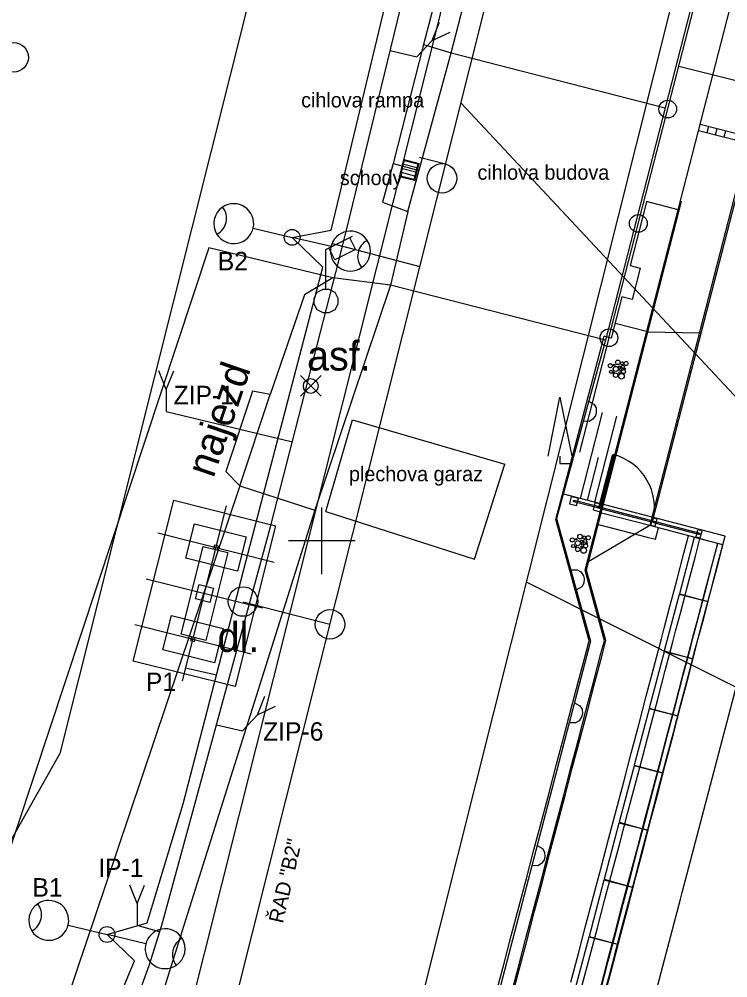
# Model space of a CAD drawing. Extents: x -733601 to -733291, y -1137892 to -1137187.
# Drawn here: x -733460.25 to -733436.26, y -1137614.8 to -1137582.33 of the extents above; entities that cross this region are included whole.
import ezdxf

# ---------------------------------------------------------------- set-up
doc = ezdxf.new("R2010")
doc.units = 0
for name, color, linetype in [('Default', 7, 'Continuous'), ('Krizky_Hektom_sit', 7, 'Continuous'), ('SIT_PROJ', 7, 'Continuous'), ('SIT_PUV_BUS', 7, 'Continuous'), ('SIT_PUV_ZELEZNICE', 7, 'Continuous')]:
    doc.layers.add(name, color=color, linetype=linetype)

# ---------------------------------------------------------------- blocks, each defined once
blk = doc.blocks.new('DOPRAVA_4$0$SYMB1230')
at = {"layer": 'Default'}
for p, q in [((-0.1, -0.329897), (-0.1, -0.020619)), ((0, -0.020619), (0, -0.329897)), ((0.1, -0.020619), (0.1, -0.329897)), ((-0.1, -0.325773), (-0.1, -0.329897))]:
    blk.add_line(p, q, dxfattribs=at)
for points in [[(-0.2, 0), (0.2, 0), (0.2, -0.35), (-0.2, -0.35)], [(-0.182831, -0.020619), (0.181696, -0.020619), (0.181696, -0.329897), (-0.182831, -0.329897)]]:
    blk.add_lwpolyline(points, close=True, dxfattribs=at)
blk = doc.blocks.new('novy_s_2r')
at = {"layer": 'Default'}
for p in [(502.569, 387.82), (502.559, 384.813)]:
    blk.add_line(p, (502.564, 386.316), dxfattribs=at)
blk.add_circle((502.564, 386.316), 0.298, dxfattribs=at)
blk.add_circle((502.564, 386.316), 0.298, dxfattribs=at)
blk.add_circle((502.564, 386.316), 0.298, dxfattribs=at)
blk.add_circle((502.564, 386.316), 0.298, dxfattribs=at)
for centre, radius, start, end in [((502.571, 388.57), 0.75, 46.9837, 135.4673), ((502.571, 388.57), 0.75, 46.9837, 135.4673), ((502.571, 388.57), 0.75, 135.4683, 46.9828), ((502.55, 389.547), 0.684, 221.2842, 321.1668), ((502.55, 389.547), 0.684, 221.2842, 321.1668), ((502.556, 384.063), 0.75, 315.4683, 226.9828), ((502.577, 383.086), 0.684, 41.2842, 141.1668), ((502.577, 383.086), 0.684, 41.2842, 141.1668), ((502.556, 384.063), 0.75, 226.9837, 315.4673), ((502.556, 384.063), 0.75, 226.9837, 315.4673)]:
    blk.add_arc(centre, radius, start, end, dxfattribs=at)
blk = doc.blocks.new('VY1')
at = {"layer": 'Default'}
for q in [(-50, 275), (50, 275), (0, 0)]:
    blk.add_line((0, 150), q, dxfattribs=at)
blk = doc.blocks.new('POINT_DISPLAY')
at = {"layer": 'Default'}
for p, q in [((-0.7, -0.7), (0.7, 0.7)), ((-0.7, 0.7), (0.7, -0.7))]:
    blk.add_line(p, q, dxfattribs=at)
blk.add_circle((0, 0), 0.5, dxfattribs=at)
blk = doc.blocks.new('vytyc_bod_MP')
at = {"layer": 'Default'}
blk.add_blockref('POINT_DISPLAY', (0, 0), dxfattribs=at)

msp = doc.modelspace()

# ---------------------------------------------------------------- linework, layer by layer
at = {"layer": 'Krizky_Hektom_sit'}
for p, q in [((-733450, -1137601.131), (-733450, -1137598.869)), ((-733448.869, -1137600), (-733451.131, -1137600))]:
    msp.add_line(p, q, dxfattribs=at)
at = {"layer": 'SIT_PROJ'}
for p, q in [((-733440.281, -1137593.122), (-733430.325, -1137554.381)), ((-733454.719, -1137604.745), (-733453.228, -1137598.809)), ((-733455.553, -1137599.731), (-733451.615, -1137600.72)), ((-733455.943, -1137601.283), (-733452.005, -1137602.272)), ((-733456.332, -1137602.835), (-733452.394, -1137603.823))]:
    msp.add_line(p, q, dxfattribs=at)
for points in [[(-733457.917, -1137622.364), (-733458.777, -1137620.095), (-733456.339, -1137614.218), (-733457.273, -1137613.333), (-733455.913, -1137612.939), (-733454.69, -1137608.9), (-733452.562, -1137600.661), (-733449.967, -1137590.732), (-733451.007, -1137589.721), (-733449.679, -1137589.475), (-733444.067, -1137566.075), (-733444.902, -1137565.405), (-733443.754, -1137565.269), (-733437.875, -1137541.673), (-733438.793, -1137541.042), (-733437.71, -1137541.027), (-733436.525, -1137536.63), (-733452.133, -1137532.662), (-733452.807, -1137531.541)], [(-733456.299, -1137623.235), (-733433.573, -1137532.72)], [(-733443.713, -1137537.937), (-733443.53, -1137546.097), (-733458.871, -1137607.201), (-733463.551, -1137615.482)], [(-733429.102, -1137545.713), (-733449.631, -1137627.477)], [(-733457.917, -1137622.364), (-733458.523, -1137621.757), (-733455.851, -1137614.377), (-733455.422, -1137613.019), (-733451.725, -1137599.481), (-733449.522, -1137590.912), (-733449.164, -1137589.482), (-733443.392, -1137565.741), (-733438.875, -1137547.904)], [(-733454.604, -1137622.264), (-733444.427, -1137581.731)], [(-733447.684, -1137583.394), (-733446.783, -1137583.603)], [(-733437.916, -1137583.919), (-733418.568, -1137588.759), (-733418.568, -1137588.759)], [(-733445.29, -1137585.169), (-733420.477, -1137611.718), (-733420.477, -1137611.718)], [(-733446.689, -1137587.01), (-733445.808, -1137587.231)], [(-733449.644, -1137589.929), (-733446.679, -1137590.702)], [(-733440.281, -1137593.122), (-733441.276, -1137596.996)], [(-733455.265, -1137595.618), (-733450.997, -1137596.65)], [(-733455.016, -1137598.618), (-733451.563, -1137599.485), (-733452.931, -1137604.936), (-733456.384, -1137604.069), (-733455.016, -1137598.619)], [(-733453.536, -1137600.306), (-733453.503, -1137600.177), (-733453.632, -1137600.144), (-733453.665, -1137600.273), (-733453.536, -1137600.306)], [(-733443.08, -1137601.386), (-733424.737, -1137610.597), (-733424.737, -1137610.597)], [(-733452.667, -1137602.059), (-733449.724, -1137602.826)], [(-733454.315, -1137603.409), (-733454.283, -1137603.28), (-733454.412, -1137603.248), (-733454.444, -1137603.377), (-733454.315, -1137603.409)], [(-733453.568, -1137604.551), (-733454.611, -1137604.306)], [(-733453.567, -1137606.228), (-733452.689, -1137606.432)], [(-733455.5, -1137613.237), (-733456.253, -1137613.029)]]:
    msp.add_lwpolyline(points, dxfattribs=at)
for points in [[(-733454.603, -1137600.589), (-733454.311, -1137599.425), (-733452.565, -1137599.863), (-733452.857, -1137601.027)], [(-733454.764, -1137603.159), (-733454.017, -1137600.185), (-733453.183, -1137600.394), (-733453.93, -1137603.369)], [(-733454.277, -1137601.959), (-733454.155, -1137601.474), (-733453.67, -1137601.596), (-733453.792, -1137602.081)], [(-733455.382, -1137603.692), (-733455.09, -1137602.528), (-733453.344, -1137602.966), (-733453.637, -1137604.13)]]:
    msp.add_lwpolyline(points, close=True, dxfattribs=at)
for centre, radius in [((-733460.435, -1137583.625), 0.5), ((-733438.29, -1137585.374), 0.3), ((-733445.931, -1137587.721), 0.5), ((-733439.285, -1137589.248), 0.3), ((-733440.281, -1137593.122), 0.3), ((-733440.281, -1137593.122), 0.3), ((-733452.667, -1137602.054), 0.5), ((-733449.724, -1137602.827), 0.5)]:
    msp.add_circle(centre, radius, dxfattribs=at)
at = {"layer": 'SIT_PUV_BUS'}
for p, q in [((-733445.62, -1137583.47), (-733437, -1137550.03)), ((-733429.79, -1137551.88), (-733440.4, -1137593.2)), ((-733442.47, -1137567.55), (-733446.56, -1137583.19)), ((-733446.56, -1137583.19), (-733447.59, -1137587.22)), ((-733446.56, -1137583.19), (-733445.62, -1137583.47)), ((-733447.09, -1137588.85), (-733445.62, -1137583.47)), ((-733445.62, -1137583.47), (-733438.38, -1137585.33)), ((-733447.59, -1137587.22), (-733447.95, -1137588.53)), ((-733447.59, -1137587.22), (-733446.71, -1137587.46)), ((-733447.95, -1137588.53), (-733447.09, -1137588.85)), ((-733447.09, -1137588.85), (-733447.67, -1137591.34)), ((-733449.86, -1137590.13), (-733448.96, -1137589.68)), ((-733449.06, -1137589.73), (-733448.86, -1137590.13)), ((-733453.82, -1137590.07), (-733460.86, -1137611.32)), ((-733449.63, -1137591.09), (-733453.82, -1137590.07)), ((-733449.86, -1137591.48), (-733449.86, -1137590.13)), ((-733449.56, -1137590.48), (-733449.76, -1137590.08)), ((-733448.86, -1137590.13), (-733449.56, -1137590.48)), ((-733449.63, -1137591.09), (-733450.59, -1137591.67)), ((-733447.67, -1137591.34), (-733449.63, -1137591.09)), ((-733450.26, -1137591.78), (-733450.16, -1137591.58)), ((-733447.67, -1137591.34), (-733450.24, -1137598.96)), ((-733450.16, -1137591.58), (-733449.96, -1137591.48)), ((-733449.96, -1137591.48), (-733449.76, -1137591.48)), ((-733449.76, -1137591.48), (-733449.56, -1137591.58)), ((-733449.56, -1137591.58), (-733449.46, -1137591.78)), ((-733440.4, -1137593.2), (-733447.67, -1137591.34)), ((-733450.59, -1137591.67), (-733451.75, -1137595.04)), ((-733450.26, -1137591.98), (-733450.26, -1137591.78)), ((-733450.16, -1137592.18), (-733450.26, -1137591.98)), ((-733449.46, -1137591.98), (-733449.56, -1137592.18)), ((-733449.46, -1137591.78), (-733449.46, -1137591.98)), ((-733449.96, -1137592.28), (-733450.16, -1137592.18)), ((-733449.76, -1137592.28), (-733449.96, -1137592.28)), ((-733449.56, -1137592.18), (-733449.76, -1137592.28)), ((-733440.4, -1137593.2), (-733442.05, -1137599.24)), ((-733452.35, -1137594.93), (-733453.25, -1137597.65)), ((-733452.78, -1137598.14), (-733451.75, -1137595.04)), ((-733451.75, -1137595.04), (-733452.35, -1137594.93)), ((-733442.34, -1137597.13), (-733441.94, -1137595.13)), ((-733441.94, -1137595.13), (-733441.54, -1137597.13)), ((-733440.968, -1137595.272), (-733440.788, -1137595.373)), ((-733440.788, -1137595.373), (-733440.718, -1137595.496)), ((-733440.718, -1137595.496), (-733440.709, -1137595.654)), ((-733440.823, -1137595.882), (-733440.946, -1137595.952)), ((-733440.735, -1137595.75), (-733440.823, -1137595.882)), ((-733440.709, -1137595.654), (-733440.735, -1137595.75)), ((-733449.86, -1137599.01), (-733448.96, -1137595.9)), ((-733448.96, -1137595.9), (-733443.8, -1137597.4)), ((-733440.946, -1137595.952), (-733441.152, -1137595.948)), ((-733441.94, -1137597.13), (-733441.94, -1137597.38)), ((-733444.83, -1137600.62), (-733443.8, -1137597.4)), ((-733441.94, -1137597.38), (-733441.54, -1137597.38)), ((-733453.25, -1137597.65), (-733452.78, -1137598.14)), ((-733452.78, -1137598.14), (-733457.34, -1137611.69)), ((-733452.78, -1137598.14), (-733450.24, -1137598.96)), ((-733450.24, -1137598.96), (-733454.61, -1137612.85)), ((-733449.86, -1137599.01), (-733444.83, -1137600.62)), ((-733442.05, -1137599.24), (-733440.9, -1137603.4)), ((-733441.563, -1137600.983), (-733441.357, -1137600.978)), ((-733441.357, -1137600.978), (-733441.234, -1137601.048)), ((-733441.234, -1137601.048), (-733441.146, -1137601.179)), ((-733441.146, -1137601.179), (-733441.119, -1137601.275)), ((-733441.119, -1137601.275), (-733441.128, -1137601.433)), ((-733441.198, -1137601.556), (-733441.377, -1137601.657)), ((-733441.128, -1137601.433), (-733441.198, -1137601.556)), ((-733440.9, -1137603.4), (-733446.32, -1137624.09)), ((-733441.441, -1137605.481), (-733441.26, -1137605.581)), ((-733441.26, -1137605.581), (-733441.189, -1137605.703)), ((-733441.179, -1137605.86), (-733441.204, -1137605.957)), ((-733441.189, -1137605.703), (-733441.179, -1137605.86)), ((-733441.413, -1137606.161), (-733441.619, -1137606.159)), ((-733441.291, -1137606.09), (-733441.413, -1137606.161)), ((-733441.204, -1137605.957), (-733441.291, -1137606.09)), ((-733442.711, -1137610.321), (-733442.53, -1137610.421)), ((-733442.53, -1137610.421), (-733442.459, -1137610.543)), ((-733442.474, -1137610.797), (-733442.561, -1137610.93)), ((-733442.449, -1137610.7), (-733442.474, -1137610.797)), ((-733442.459, -1137610.543), (-733442.449, -1137610.7)), ((-733442.683, -1137611.001), (-733442.889, -1137610.999)), ((-733442.561, -1137610.93), (-733442.683, -1137611.001)), ((-733457.34, -1137611.69), (-733463.99, -1137631.53)), ((-733454.61, -1137612.85), (-733456.8, -1137619.8))]:
    msp.add_line(p, q, dxfattribs=at)
at = {"layer": 'SIT_PUV_ZELEZNICE'}
for p, q in [((-733437.941, -1137588.784), (-733432.439, -1137567.425)), ((-733437.249, -1137586.096), (-733435.215, -1137586.62)), ((-733437.194, -1137585.883), (-733435.16, -1137586.407)), ((-733436.958, -1137586.171), (-733436.903, -1137585.958)), ((-733436.668, -1137586.246), (-733436.613, -1137586.033)), ((-733436.377, -1137586.321), (-733436.322, -1137586.108)), ((-733438.815, -1137599.192), (-733435.554, -1137586.533)), ((-733438.766, -1137599.204), (-733435.506, -1137586.545)), ((-733441.035, -1137600.996), (-733437.818, -1137588.506)), ((-733437.866, -1137588.493), (-733437.818, -1137588.506)), ((-733441.087, -1137600.996), (-733437.941, -1137588.784)), ((-733439.004, -1137592.912), (-733440.073, -1137592.636)), ((-733439.004, -1137592.912), (-733438.956, -1137592.924)), ((-733438.956, -1137592.924), (-733437.207, -1137592.951)), ((-733437.159, -1137592.964), (-733437.207, -1137592.951)), ((-733441.247, -1137598.565), (-733440.498, -1137595.655)), ((-733440.763, -1137598.69), (-733440.013, -1137595.78)), ((-733441.005, -1137598.627), (-733440.63, -1137597.173)), ((-733440.623, -1137598.873), (-733440.158, -1137597.095)), ((-733440.577, -1137598.885), (-733440.111, -1137597.107)), ((-733440.509, -1137598.755), (-733441.851, -1137598.409)), ((-733441.554, -1137598.5), (-733441.617, -1137598.742)), ((-733441.617, -1137598.742), (-733441.376, -1137598.805)), ((-733441.312, -1137598.563), (-733441.554, -1137598.5)), ((-733440.672, -1137598.885), (-733441.471, -1137598.676)), ((-733440.66, -1137598.838), (-733441.459, -1137598.629)), ((-733441.376, -1137598.805), (-733441.312, -1137598.563)), ((-733440.755, -1137598.709), (-733440.819, -1137598.951)), ((-733440.513, -1137598.773), (-733440.755, -1137598.709)), ((-733440.577, -1137599.014), (-733440.513, -1137598.773)), ((-733438.815, -1137599.192), (-733440.509, -1137598.755)), ((-733440.819, -1137598.951), (-733440.577, -1137599.014)), ((-733438.828, -1137599.368), (-733440.606, -1137598.902)), ((-733438.816, -1137599.321), (-733440.594, -1137598.856)), ((-733438.891, -1137599.482), (-733440.536, -1137599.058)), ((-733440.636, -1137599.445), (-733438.991, -1137599.869)), ((-733438.815, -1137599.192), (-733438.891, -1137599.482)), ((-733438.86, -1137599.464), (-733438.797, -1137599.222)), ((-733436.348, -1137599.837), (-733438.815, -1137599.192)), ((-733438.652, -1137599.26), (-733438.797, -1137599.222)), ((-733437.234, -1137599.786), (-733438.762, -1137599.385)), ((-733437.221, -1137599.739), (-733438.75, -1137599.339)), ((-733438.715, -1137599.502), (-733438.652, -1137599.26)), ((-733438.891, -1137599.482), (-733440.96, -1137600.703)), ((-733436.425, -1137600.128), (-733438.891, -1137599.482)), ((-733438.86, -1137599.464), (-733438.715, -1137599.502)), ((-733438.701, -1137599.945), (-733438.599, -1137599.558)), ((-733437.332, -1137599.864), (-733437.268, -1137599.622)), ((-733437.123, -1137599.66), (-733437.268, -1137599.622)), ((-733437.187, -1137599.902), (-733437.123, -1137599.66)), ((-733438.991, -1137599.869), (-733438.701, -1137599.945)), ((-733437.395, -1137599.887), (-733437.896, -1137601.792)), ((-733436.426, -1137600.131), (-733437.395, -1137599.887)), ((-733437.332, -1137599.864), (-733437.187, -1137599.902)), ((-733437.904, -1137601.821), (-733438.405, -1137603.726)), ((-733436.934, -1137602.066), (-733437.904, -1137601.821)), ((-733437.896, -1137601.792), (-733436.932, -1137602.056)), ((-733438.413, -1137603.755), (-733438.914, -1137605.66)), ((-733437.443, -1137604), (-733438.413, -1137603.755)), ((-733438.405, -1137603.726), (-733437.44, -1137603.99)), ((-733438.922, -1137605.689), (-733439.424, -1137607.594)), ((-733437.952, -1137605.934), (-733438.922, -1137605.689)), ((-733438.914, -1137605.66), (-733437.95, -1137605.924)), ((-733439.431, -1137607.623), (-733439.934, -1137609.527)), ((-733438.462, -1137607.868), (-733439.431, -1137607.623)), ((-733439.424, -1137607.594), (-733438.459, -1137607.858)), ((-733439.941, -1137609.556), (-733440.444, -1137611.461)), ((-733438.972, -1137609.802), (-733439.941, -1137609.556)), ((-733439.934, -1137609.527), (-733438.969, -1137609.792)), ((-733440.444, -1137611.461), (-733439.48, -1137611.726)), ((-733440.452, -1137611.49), (-733440.954, -1137613.395)), ((-733439.482, -1137611.736), (-733440.452, -1137611.49)), ((-733440.954, -1137613.395), (-733439.99, -1137613.66)), ((-733440.962, -1137613.424), (-733441.464, -1137615.329)), ((-733439.992, -1137613.669), (-733440.962, -1137613.424))]:
    msp.add_line(p, q, dxfattribs=at)
for points in [[(-733437.941, -1137588.784), (-733439.005, -1137588.505), (-733439.036, -1137588.612), (-733439.566, -1137590.669), (-733439.218, -1137590.759), (-733439.492, -1137591.824), (-733439.841, -1137591.735), (-733440.2, -1137593.129), (-733440.44, -1137593.066)], [(-733473.591, -1137751.638), (-733472.603, -1137747.76), (-733470.135, -1137738.069), (-733467.666, -1137728.379), (-733465.198, -1137718.688), (-733462.729, -1137708.998), (-733460.26, -1137699.307), (-733457.792, -1137689.617), (-733455.323, -1137679.926), (-733452.855, -1137670.236), (-733450.386, -1137660.545), (-733448.734, -1137654.061), (-733447.917, -1137650.855), (-733445.432, -1137641.168), (-733442.928, -1137631.487), (-733440.405, -1137621.811), (-733437.862, -1137612.139), (-733437.8, -1137611.906), (-733435.314, -1137602.469), (-733432.775, -1137592.797), (-733432.613, -1137592.177)], [(-733440.951, -1137603.382), (-733442.078, -1137599.27), (-733440.44, -1137593.066)], [(-733438.891, -1137599.482), (-733440.536, -1137599.058)], [(-733441.568, -1137614.94), (-733441.313, -1137613.972), (-733441.058, -1137613.003), (-733440.802, -1137612.034), (-733440.547, -1137611.066), (-733440.291, -1137610.098), (-733440.036, -1137609.13), (-733439.78, -1137608.161), (-733439.525, -1137607.193), (-733439.27, -1137606.225), (-733439.015, -1137605.256), (-733438.76, -1137604.288), (-733438.505, -1137603.319), (-733438.41, -1137602.959), (-733438.25, -1137602.351), (-733437.995, -1137601.382), (-733437.741, -1137600.414), (-733437.585, -1137599.824)], [(-733441.181, -1137615.042), (-733440.926, -1137614.073), (-733440.671, -1137613.105), (-733440.416, -1137612.136), (-733440.16, -1137611.168), (-733439.904, -1137610.2), (-733439.649, -1137609.232), (-733439.394, -1137608.263), (-733439.138, -1137607.295), (-733438.883, -1137606.327), (-733438.628, -1137605.358), (-733438.373, -1137604.39), (-733438.118, -1137603.421), (-733438.023, -1137603.061), (-733437.863, -1137602.453), (-733437.608, -1137601.484), (-733437.354, -1137600.515), (-733437.199, -1137599.925)], [(-733440.582, -1137615.2), (-733440.327, -1137614.231), (-733440.071, -1137613.263), (-733439.816, -1137612.295), (-733439.561, -1137611.326), (-733439.305, -1137610.358), (-733439.049, -1137609.39), (-733438.794, -1137608.421), (-733438.539, -1137607.453), (-733438.283, -1137606.485), (-733438.028, -1137605.516), (-733437.773, -1137604.548), (-733437.518, -1137603.579), (-733437.424, -1137603.219), (-733437.263, -1137602.61), (-733437.009, -1137601.642), (-733436.754, -1137600.673), (-733436.599, -1137600.082)], [(-733440.555, -1137615.207), (-733440.302, -1137614.238), (-733440.048, -1137613.269), (-733439.794, -1137612.301), (-733439.541, -1137611.332), (-733439.287, -1137610.363), (-733439.033, -1137609.394), (-733438.78, -1137608.426), (-733438.526, -1137607.457), (-733438.272, -1137606.488), (-733438.019, -1137605.519), (-733437.765, -1137604.55), (-733437.511, -1137603.581), (-733437.417, -1137603.221), (-733437.257, -1137602.612), (-733437.004, -1137601.643), (-733436.75, -1137600.674), (-733436.595, -1137600.083)], [(-733440.408, -1137615.246), (-733440.153, -1137614.277), (-733439.897, -1137613.309), (-733439.642, -1137612.341), (-733439.386, -1137611.372), (-733439.131, -1137610.404), (-733438.875, -1137609.436), (-733438.62, -1137608.467), (-733438.365, -1137607.499), (-733438.109, -1137606.53), (-733437.854, -1137605.562), (-733437.599, -1137604.593), (-733437.344, -1137603.625), (-733437.249, -1137603.265), (-733437.089, -1137602.656), (-733436.835, -1137601.687), (-733436.58, -1137600.719), (-733436.348, -1137599.837)], [(-733440.381, -1137615.252), (-733440.128, -1137614.284), (-733439.874, -1137613.315), (-733439.62, -1137612.346), (-733439.367, -1137611.378), (-733439.113, -1137610.409), (-733438.859, -1137609.44), (-733438.606, -1137608.471), (-733438.352, -1137607.502), (-733438.098, -1137606.533), (-733437.844, -1137605.565), (-733437.591, -1137604.596), (-733437.337, -1137603.627), (-733437.243, -1137603.266), (-733437.083, -1137602.658), (-733436.83, -1137601.689), (-733436.576, -1137600.72), (-733436.345, -1137599.838)], [(-733440.434, -1137603.38), (-733441.087, -1137600.996)], [(-733440.382, -1137603.379), (-733441.035, -1137600.996)], [(-733446.408, -1137624.136), (-733446.381, -1137624.034), (-733446.128, -1137623.065), (-733445.875, -1137622.095), (-733445.621, -1137621.126), (-733445.367, -1137620.157), (-733445.113, -1137619.188), (-733444.859, -1137618.218), (-733444.605, -1137617.249), (-733444.35, -1137616.28), (-733444.096, -1137615.311), (-733443.841, -1137614.342), (-733443.586, -1137613.373), (-733443.33, -1137612.404), (-733443.075, -1137611.435), (-733442.819, -1137610.466), (-733442.563, -1137609.498), (-733442.308, -1137608.53), (-733442.053, -1137607.562), (-733441.797, -1137606.594), (-733441.542, -1137605.626), (-733441.287, -1137604.658), (-733441.032, -1137603.69), (-733440.951, -1137603.382)], [(-733443.612, -1137615.438), (-733443.357, -1137614.469), (-733443.102, -1137613.5), (-733442.847, -1137612.531), (-733442.591, -1137611.562), (-733442.335, -1137610.594), (-733442.08, -1137609.626), (-733441.824, -1137608.658), (-733441.569, -1137607.69), (-733441.314, -1137606.721), (-733441.059, -1137605.753), (-733440.804, -1137604.785), (-733440.549, -1137603.817), (-733440.434, -1137603.38)], [(-733443.564, -1137615.451), (-733443.309, -1137614.482), (-733443.054, -1137613.513), (-733442.798, -1137612.544), (-733442.543, -1137611.575), (-733442.287, -1137610.607), (-733442.032, -1137609.638), (-733441.776, -1137608.67), (-733441.521, -1137607.702), (-733441.266, -1137606.734), (-733441.01, -1137605.766), (-733440.755, -1137604.798), (-733440.5, -1137603.83), (-733440.382, -1137603.379)]]:
    msp.add_lwpolyline(points, dxfattribs=at)
for centre, radius in [((-733439.978, -1137593.954), 0.0777), ((-733439.836, -1137593.983), 0.0522), ((-733439.699, -1137593.992), 0.0686), ((-733440.237, -1137594.067), 0.0687), ((-733440.211, -1137594.275), 0.0528), ((-733440.05, -1137594.177), 0.0864), ((-733440.103, -1137594.04), 0.0259), ((-733439.922, -1137594.114), 0.0388), ((-733439.887, -1137594.205), 0.0404), ((-733439.804, -1137594.105), 0.0528), ((-733439.787, -1137594.268), 0.0672), ((-733439.75, -1137594.177), 0.0278), ((-733440.132, -1137594.302), 0.027), ((-733440.055, -1137594.388), 0.0752), ((-733439.856, -1137594.423), 0.0954), ((-733439.915, -1137594.307), 0.0323), ((-733440.134, -1137597.101), 0.0241), ((-733441.465, -1137598.653), 0.0241), ((-733440.666, -1137598.862), 0.0241), ((-733440.6, -1137598.879), 0.0241), ((-733438.822, -1137599.345), 0.0241), ((-733438.756, -1137599.362), 0.0241), ((-733441.26, -1137599.854), 0.0777), ((-733437.228, -1137599.762), 0.0241), ((-733441.519, -1137599.967), 0.0687), ((-733441.332, -1137600.077), 0.0864), ((-733441.385, -1137599.94), 0.0259), ((-733441.204, -1137600.014), 0.0388), ((-733441.169, -1137600.105), 0.0404), ((-733441.118, -1137599.883), 0.0522), ((-733441.086, -1137600.005), 0.0528), ((-733441.068, -1137600.168), 0.0672), ((-733441.032, -1137600.077), 0.0278), ((-733440.981, -1137599.892), 0.0686), ((-733441.493, -1137600.175), 0.0528), ((-733441.414, -1137600.202), 0.027), ((-733441.337, -1137600.288), 0.0752), ((-733441.138, -1137600.323), 0.0954), ((-733441.196, -1137600.207), 0.0323)]:
    msp.add_circle(centre, radius, dxfattribs=at)
msp.add_arc((-733440.6, -1137598.879), 1.862, 345.3262, 75.3262, dxfattribs=at)

# ---------------------------------------------------------------- block references
at = {"layer": 'SIT_PROJ'}
for name, p, xscale, yscale, rotation in [('VY1', (-733446.783, -1137583.603), 0.005, 0.004999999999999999, -43.302577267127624), ('DOPRAVA_4$0$SYMB1230', (-733447.295, -1137587.375), 1.4999999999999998, 1.5, 75.437), ('novy_s_2r', (-733214.434, -1138108.855), 0.9000000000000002, 0.9, 76.94986106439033), ('VY1', (-733452.689, -1137606.432), 0.005, 0.004999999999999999, -43.302577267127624), ('novy_s_2r', (-733224.727, -1138134.282), 0.9, 0.9000000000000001, 76.50628946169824)]:
    msp.add_blockref(name, p, dxfattribs=dict(at, xscale=xscale, yscale=yscale, rotation=rotation))
for name, p, xscale, yscale in [('VY1', (-733455.265, -1137595.618), 0.005, 0.005), ('vytyc_bod_MP', (-733450.375, -1137594.753), 0.5, 0.5), ('VY1', (-733456.253, -1137613.029), 0.005, 0.005)]:
    msp.add_blockref(name, p, dxfattribs=dict(at, xscale=xscale, yscale=yscale))

# ---------------------------------------------------------------- texts
for s, height, rotation, p in [('B2', 0.625, 360, (-733453.523, -1137590.836)), ('ZIP-1', 0.625, 360, (-733455.019, -1137595.373)), ('P1', 0.625, 360, (-733455.957, -1137605.087)), ('ZIP-6', 0.625, 360, (-733451.988, -1137606.766)), ('ŘAD "B2"', 0.5, 77.0268, (-733451.32, -1137612.976)), ('IP-1', 0.625, 360, (-733457.569, -1137611.385)), ('B1', 0.625, 360, (-733459.799, -1137612.046))]:
    msp.add_text(s, height=height, rotation=rotation, dxfattribs=at).set_placement(p)
at = {"layer": 'SIT_PUV_BUS'}
for s, height, p in [('cihlova rampa', 0.5, (-733450.7, -1137585.32)), ('schody', 0.5, (-733449.39, -1137587.95)), ('cihlova budova', 0.5, (-733444.73, -1137587.77)), ('asf.', 1, (-733450.5, -1137594.23)), ('plechova garaz', 0.5, (-733449.08, -1137597.98)), ('dl.', 1, (-733453.53, -1137603.76))]:
    msp.add_text(s, height=height, dxfattribs=at).set_placement(p)
msp.add_text('najezd', height=1, rotation=71.1, dxfattribs=at).set_placement((-733453.67, -1137597.9))

doc.saveas('drawing.dxf')
